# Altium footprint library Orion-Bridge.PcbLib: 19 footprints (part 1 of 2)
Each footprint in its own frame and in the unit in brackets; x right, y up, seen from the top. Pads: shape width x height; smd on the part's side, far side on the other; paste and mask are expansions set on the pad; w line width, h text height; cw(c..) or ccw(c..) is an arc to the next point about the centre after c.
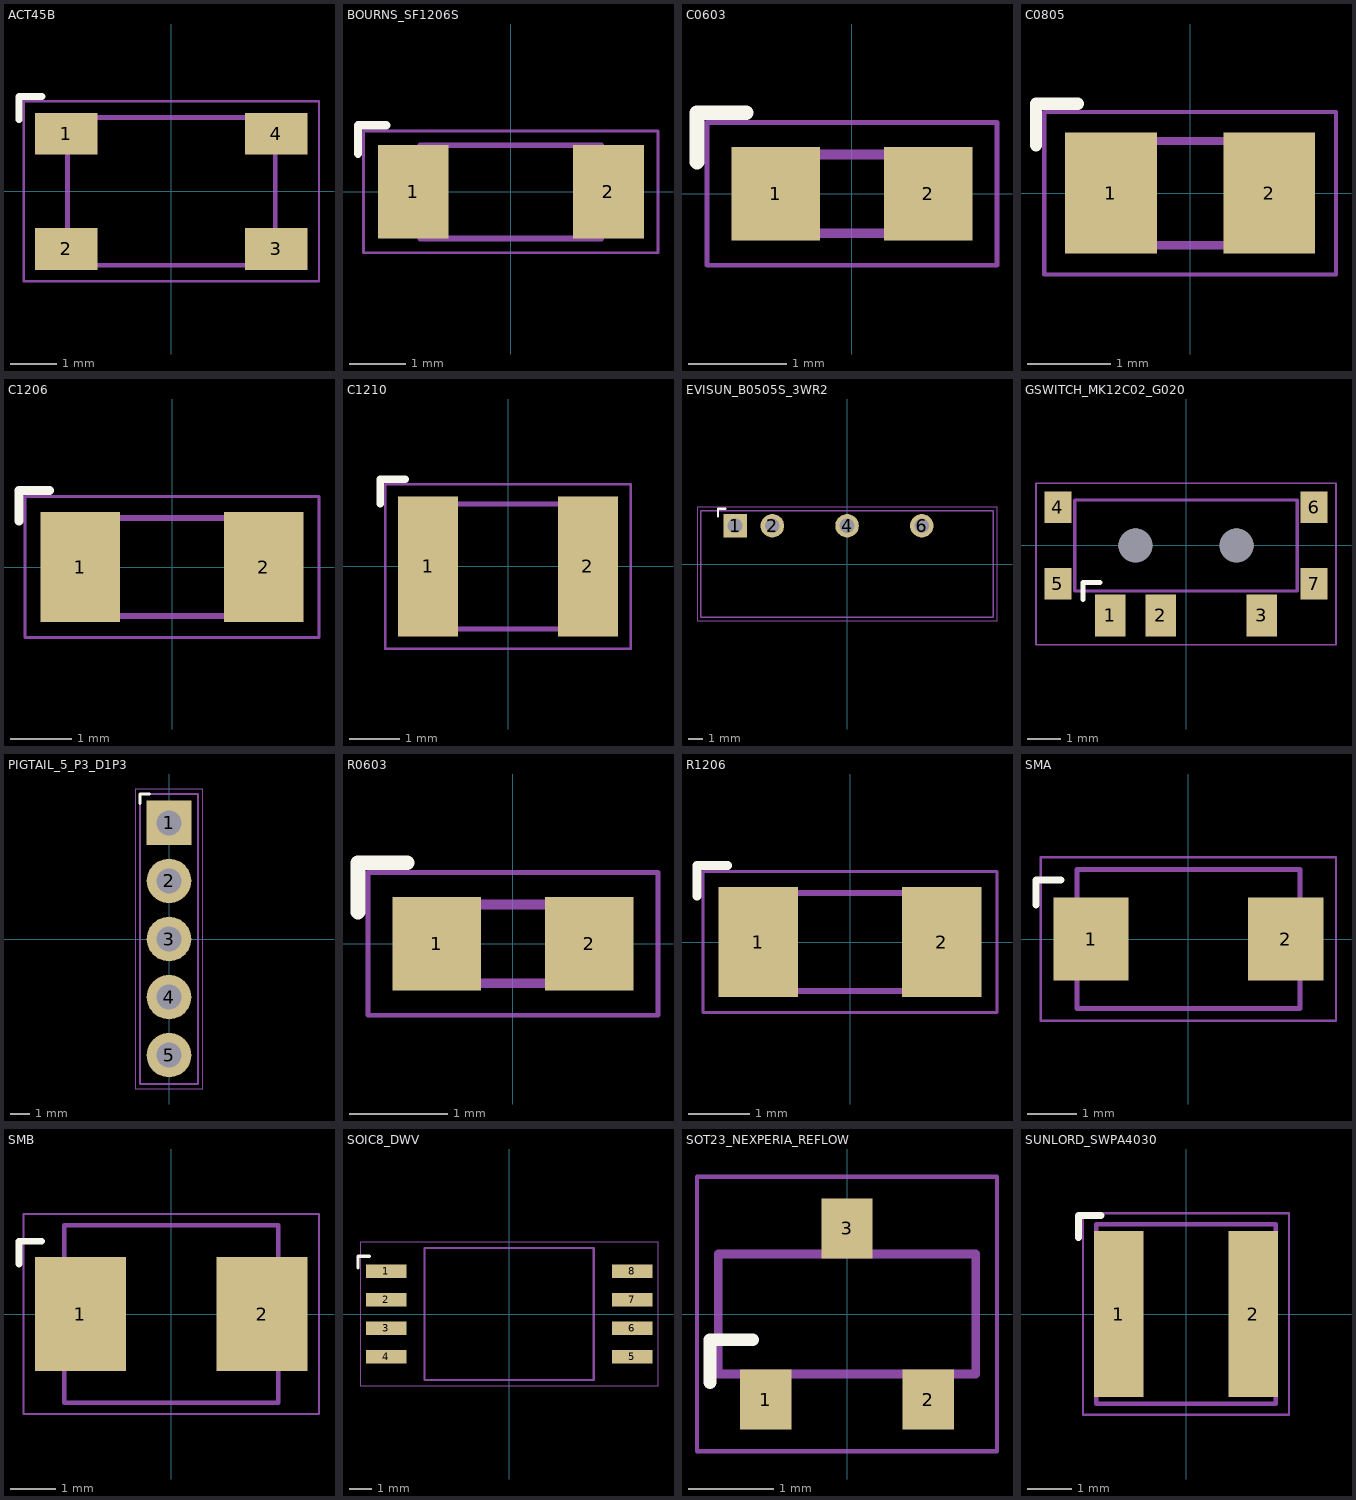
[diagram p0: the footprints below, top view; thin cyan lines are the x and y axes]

## ACT45B [mm] "TDK ACT45B recommended lands; windings 1-4 and 2-3"
height 2.8
pads (4):
  rect 1.35x0.9 smd: 1(-2.275,1.25) 2(-2.275,-1.25) 3(2.275,-1.25) 4(2.275,1.25)
Top Overlay:
  lines w0.15: -3.3,1.55 -3.3,2.05 -2.8,2.05
Component bodies:
  lines w0.1: -2.25,-1.6 2.25,-1.6 2.25,1.6 -2.25,1.6 -2.25,-1.6
Courtyards:
  lines w0.05: -3.2,-1.95 3.2,-1.95 3.2,1.95 -3.2,1.95 -3.2,-1.95
3D body: height 2.8, standoff 0.08, extent -2.25,-1.6 2.25,1.6
3D body: height 0.22, standoff 0.03, extent -2.525,1.01 -1.95,1.49
3D body: height 0.22, standoff 0.03, extent -2.525,-1.49 -1.95,-1.01
3D body: height 0.22, standoff 0.03, extent 1.95,-1.49 2.525,-1.01
3D body: height 0.22, standoff 0.03, extent 1.95,1.01 2.525,1.49

## BOURNS_SF1206S [mm] "Bourns SF-1206S recommended land pattern: total X span 4.7, inner gap 2.2, pad Y 1.65; maximum body envelope. No polarity."
height 0.7
pads (2):
  rect 1.25x1.65 smd: 1(-1.725,0) 2(1.725,0)
Top Overlay:
  lines w0.15: -2.7,0.675 -2.7,1.175 -2.2,1.175
Component bodies:
  lines w0.1: -1.6,-0.825 1.6,-0.825 1.6,0.825 -1.6,0.825 -1.6,-0.825
Courtyards:
  lines w0.05: -2.6,-1.075 2.6,-1.075 2.6,1.075 -2.6,1.075 -2.6,-1.075
3D body: height 0.7, standoff 0.08, extent -1.6,-0.825 1.6,0.825
3D body: height 0.71, standoff 0.03, extent -1.6,-0.833 -1.22,0.833
3D body: height 0.71, standoff 0.03, extent 1.22,-0.833 1.6,0.833

## C0603 [mm] "IPC-style 0603 solder lands; selected MPN dimensions reviewed separately."
height 0.8
pads (2):
  rect 0.9x0.95 smd: 1(-0.775,0) 2(0.775,0)
Top Overlay:
  lines w0.15: -1.575,0.325 -1.575,0.825 -1.075,0.825
Component bodies:
  lines w0.1: -0.8,-0.4 0.8,-0.4 0.8,0.4 -0.8,0.4 -0.8,-0.4
Courtyards:
  lines w0.05: -1.475,-0.725 1.475,-0.725 1.475,0.725 -1.475,0.725 -1.475,-0.725
3D body: height 0.8, standoff 0.08, extent -0.8,-0.4 0.8,0.4
3D body: height 0.81, standoff 0.03, extent -0.8,-0.407 -0.512,0.407
3D body: height 0.81, standoff 0.03, extent 0.512,-0.407 0.8,0.407

## C0805 [mm] "IPC-style 0805 solder lands; selected MPN dimensions reviewed separately."
height 0.8
pads (2):
  rect 1.1x1.45 smd: 1(-0.95,0) 2(0.95,0)
Top Overlay:
  lines w0.15: -1.85,0.575 -1.85,1.075 -1.35,1.075
Component bodies:
  lines w0.1: -1,-0.625 1,-0.625 1,0.625 -1,0.625 -1,-0.625
Courtyards:
  lines w0.05: -1.75,-0.975 1.75,-0.975 1.75,0.975 -1.75,0.975 -1.75,-0.975
3D body: height 0.8, standoff 0.08, extent -1,-0.625 1,0.625
3D body: height 0.81, standoff 0.03, extent -1,-0.633 -0.64,0.633
3D body: height 0.81, standoff 0.03, extent 0.64,-0.633 1,0.633

## C1206 [mm] "IPC-style 1206 solder lands; selected MPN dimensions reviewed separately."
height 1.5
pads (2):
  rect 1.3x1.8 smd: 1(-1.5,0) 2(1.5,0)
Top Overlay:
  lines w0.15: -2.5,0.75 -2.5,1.25 -2,1.25
Component bodies:
  lines w0.1: -1.6,-0.8 1.6,-0.8 1.6,0.8 -1.6,0.8 -1.6,-0.8
Courtyards:
  lines w0.05: -2.4,-1.15 2.4,-1.15 2.4,1.15 -2.4,1.15 -2.4,-1.15
3D body: height 1.5, standoff 0.08, extent -1.6,-0.8 1.6,0.8
3D body: height 1.52, standoff 0.03, extent -1.6,-0.807 -1.22,0.807
3D body: height 1.52, standoff 0.03, extent 1.22,-0.807 1.6,0.807

## C1210 [mm] "Samsung CL32B106KBJNNNE body3.2x2.5mm, nominal1210 land pattern selected."
height 2.7
pads (2):
  rect 1.2x2.8 smd: 1(-1.6,0) 2(1.6,0)
Top Overlay:
  lines w0.15: -2.55,1.25 -2.55,1.75 -2.05,1.75
Component bodies:
  lines w0.1: -1.6,-1.25 1.6,-1.25 1.6,1.25 -1.6,1.25 -1.6,-1.25
Courtyards:
  lines w0.05: -2.45,-1.65 2.45,-1.65 2.45,1.65 -2.45,1.65 -2.45,-1.65
3D body: height 2.7, standoff 0.08, extent -1.6,-1.25 1.6,1.25
3D body: height 2.72, standoff 0.03, extent -1.6,-1.258 -1.22,1.258
3D body: height 2.72, standoff 0.03, extent 1.22,-1.258 1.6,1.258

## EVISUN_B0505S_3WR2 [mm] "EVISUN p4: nominal19.65x7x10.16mm, unspecified body tolerance+/-0.25mm, lead1 x=2.21 from body left, pitch1-2=2.54/2-4=5.08/4-6=5.08mm. Pin row .90mm from long body edge. Bottom view mirrored vertically to PCB TOP: row Y=+2.60mm. Finished holes1.00mm, annulus.30mm. Primary/secondary pad copper gap3.48mm."
height 10.41
pads (4):
  rect 1.6x1.6 hole 1 paste-10: 1(-7.615,2.6)
  round 1.6 hole 1 paste-10: 2(-5.075,2.6) 4(0.005,2.6) 6(5.085,2.6)
Top Overlay:
  lines w0.15: -8.765,3.25 -8.765,3.75 -8.265,3.75
Component bodies:
  lines w0.1: -9.95,-3.625 9.95,-3.625 9.95,3.625 -9.95,3.625 -9.95,-3.625
Courtyards:
  lines w0.05: -10.2,-3.875 10.2,-3.875 10.2,3.875 -10.2,3.875 -10.2,-3.875
3D body: height 10.31, standoff 0.15, extent -9.825,-3.5 9.825,3.5
3D body: height 10.33, standoff 10.31, extent -8.2,-2.55 8.2,2.55
3D body: height 0.45, standoff -2.5, extent -7.865,2.35 -7.365,2.85
3D body: height 0.45, standoff -2.5, extent -5.325,2.35 -4.825,2.85
3D body: height 0.45, standoff -2.5, extent -0.245,2.35 0.255,2.85
3D body: height 0.45, standoff -2.5, extent 4.835,2.35 5.335,2.85

## GSWITCH_MK12C02_G020 [mm] "All shell tabs tied only to GND_LOGIC. No paste in NPTH. Keep travel envelope clear. Pin numbers1/2/3 assigned left/common/right as manufacturer circuit A/B; mounting pads4-7 are local library assignments."
height 1.4
pads (9):
  rect 0.9x1.25 smd: 1(-2.25,-2.075) 2(-0.75,-2.075) 3(2.25,-2.075)
  rect 0.8x0.93 smd: 4(-3.8,1.135) 5(-3.8,-1.135) 6(3.8,1.135) 7(3.8,-1.135)
  round 1 hole 1 unplated paste-10: ""(-1.5,0) ""(1.5,0)
Top Overlay:
  lines w0.15: -3.05,-1.6 -3.05,-1.1 -2.55,-1.1
Component bodies:
  lines w0.1: -3.3,-1.35 3.3,-1.35 3.3,1.35 -3.3,1.35 -3.3,-1.35
Courtyards:
  lines w0.05: -4.45,-2.95 4.45,-2.95 4.45,1.85 -4.45,1.85 -4.45,-2.95
3D body: height 1.25, standoff 0.05, extent -3.3,-1.35 3.3,1.35
3D body: height 1.4, standoff 1.25, extent -3.25,-1.3 3.25,1.3
3D body: height 1.25, standoff 0.15, extent -1.4,1.3 -0.1,3.35
3D body: height 0.15, standoff 0.02, extent -2.7,-2.7 -1.8,-1.45
3D body: height 0.15, standoff 0.02, extent -1.2,-2.7 -0.3,-1.45
3D body: height 0.15, standoff 0.02, extent 1.8,-2.7 2.7,-1.45
3D body: height 0.15, standoff 0.02, extent -4.2,0.67 -3.4,1.6
3D body: height 0.15, standoff 0.02, extent -4.2,-1.6 -3.4,-0.67
3D body: height 0.15, standoff 0.02, extent 3.4,0.67 4.2,1.6
3D body: height 0.15, standoff 0.02, extent 3.4,-1.6 4.2,-0.67

## PIGTAIL_5_P3_D1P3 [mm] "Designed carrier wire-solder interface, 3.0 pitch, 1.3 finished-hole target, 0.5 radial annulus. Pin numbering is logical NMEA: 1 shield, 2 NET-S, 3 NET-C, 4 CAN-H, 5 CAN-L. Cable and strain relief still require a physical selection."
height 3
pads (5):
  rect 2.3x2.3 hole 1.3 paste-10: 1(0,6)
  round 2.3 hole 1.3 paste-10: 2(0,3) 3(0,0) 4(0,-3) 5(0,-6)
Top Overlay:
  lines w0.15: -1.5,7 -1.5,7.5 -1,7.5
Component bodies:
  lines w0.1: -1.5,-7.5 1.5,-7.5 1.5,7.5 -1.5,7.5 -1.5,-7.5
Courtyards:
  lines w0.05: -1.75,-7.75 1.75,-7.75 1.75,7.75 -1.75,7.75 -1.75,-7.75
3D body: height 0.06, standoff 0.03, extent -1.15,4.85 1.15,5.03
3D body: height 0.06, standoff 0.03, extent -1.15,6.97 1.15,7.15
3D body: height 0.06, standoff 0.03, extent -1.15,5.03 -0.97,6.97
3D body: height 0.06, standoff 0.03, extent 0.97,5.03 1.15,6.97
3D body: height 0.06, standoff 0.03, extent -1.15,1.85 1.15,2.03
3D body: height 0.06, standoff 0.03, extent -1.15,3.97 1.15,4.15
3D body: height 0.06, standoff 0.03, extent -1.15,2.03 -0.97,3.97
3D body: height 0.06, standoff 0.03, extent 0.97,2.03 1.15,3.97
3D body: height 0.06, standoff 0.03, extent -1.15,-1.15 1.15,-0.97
3D body: height 0.06, standoff 0.03, extent -1.15,0.97 1.15,1.15
3D body: height 0.06, standoff 0.03, extent -1.15,-0.97 -0.97,0.97
3D body: height 0.06, standoff 0.03, extent 0.97,-0.97 1.15,0.97
3D body: height 0.06, standoff 0.03, extent -1.15,-4.15 1.15,-3.97
3D body: height 0.06, standoff 0.03, extent -1.15,-2.03 1.15,-1.85
3D body: height 0.06, standoff 0.03, extent -1.15,-3.97 -0.97,-2.03
3D body: height 0.06, standoff 0.03, extent 0.97,-3.97 1.15,-2.03
3D body: height 0.06, standoff 0.03, extent -1.15,-7.15 1.15,-6.97
3D body: height 0.06, standoff 0.03, extent -1.15,-5.03 1.15,-4.85
3D body: height 0.06, standoff 0.03, extent -1.15,-6.97 -0.97,-5.03
3D body: height 0.06, standoff 0.03, extent 0.97,-6.97 1.15,-5.03

## R0603 [mm] "IPC-style 0603 solder lands; selected MPN dimensions reviewed separately."
height 0.8
pads (2):
  rect 0.9x0.95 smd: 1(-0.775,0) 2(0.775,0)
Top Overlay:
  lines w0.15: -1.575,0.325 -1.575,0.825 -1.075,0.825
Component bodies:
  lines w0.1: -0.8,-0.4 0.8,-0.4 0.8,0.4 -0.8,0.4 -0.8,-0.4
Courtyards:
  lines w0.05: -1.475,-0.725 1.475,-0.725 1.475,0.725 -1.475,0.725 -1.475,-0.725
3D body: height 0.8, standoff 0.08, extent -0.8,-0.4 0.8,0.4
3D body: height 0.81, standoff 0.03, extent -0.8,-0.407 -0.512,0.407
3D body: height 0.81, standoff 0.03, extent 0.512,-0.407 0.8,0.407

## R1206 [mm] "IPC-style 1206 solder lands; selected MPN dimensions reviewed separately."
height 1.5
pads (2):
  rect 1.3x1.8 smd: 1(-1.5,0) 2(1.5,0)
Top Overlay:
  lines w0.15: -2.5,0.75 -2.5,1.25 -2,1.25
Component bodies:
  lines w0.1: -1.6,-0.8 1.6,-0.8 1.6,0.8 -1.6,0.8 -1.6,-0.8
Courtyards:
  lines w0.05: -2.4,-1.15 2.4,-1.15 2.4,1.15 -2.4,1.15 -2.4,-1.15
3D body: height 1.5, standoff 0.08, extent -1.6,-0.8 1.6,0.8
3D body: height 1.52, standoff 0.03, extent -1.6,-0.807 -1.22,0.807
3D body: height 1.52, standoff 0.03, extent 1.22,-0.807 1.6,0.807

## SMA [mm] "MDD SS12-SS1200 Rev2025A3 p3 / SS22-SS2200 Rev2024A4 p3 suggested SMA pattern: pad1.52x1.68, centrepitch3.93, innergap2.41, totalX5.45mm. Maxbody4.5x2.8x2.45; pin1Kleft,2Aright. Visually checked selected C2480/C14238 PDFs."
height 2.45
pads (2):
  rect 1.52x1.68 smd: 1(-1.965,0) 2(1.965,0)
Top Overlay:
  lines w0.15: -3.075,0.69 -3.075,1.19 -2.575,1.19
Component bodies:
  lines w0.1: -2.25,-1.4 2.25,-1.4 2.25,1.4 -2.25,1.4 -2.25,-1.4
Courtyards:
  lines w0.05: -2.975,-1.65 2.975,-1.65 2.975,1.65 -2.975,1.65 -2.975,-1.65
3D body: height 2.45, standoff 0.08, extent -2.25,-1.4 2.25,1.4
3D body: height 0.2, standoff 0.03, extent -2.54,-0.84 -1.39,0.84
3D body: height 0.2, standoff 0.03, extent 1.39,-0.84 2.54,0.84
3D body: height 2.46, standoff 2.45, extent -1.52,-1.372 -1.27,1.372

## SMB [mm] "BORN SMBJ Series Rev2022-Jan-1-A p7 manufacturer pattern: pad2.0x2.5mm, innergap2.0mm, centres+/-2.0mm; maxbody4.7x3.9x2.5; pin1Kleft,2Aright. Visually checked selected C152104 PDF."
height 2.5
pads (2):
  rect 2x2.5 smd: 1(-2,0) 2(2,0)
Top Overlay:
  lines w0.15: -3.35,1.1 -3.35,1.6 -2.85,1.6
Component bodies:
  lines w0.1: -2.35,-1.95 2.35,-1.95 2.35,1.95 -2.35,1.95 -2.35,-1.95
Courtyards:
  lines w0.05: -3.25,-2.2 3.25,-2.2 3.25,2.2 -3.25,2.2 -3.25,-2.2
3D body: height 2.5, standoff 0.08, extent -2.35,-1.95 2.35,1.95
3D body: height 0.2, standoff 0.03, extent -2.575,-1.05 -1.425,1.05
3D body: height 0.2, standoff 0.03, extent 1.425,-1.05 2.575,1.05
3D body: height 2.51, standoff 2.5, extent -1.582,-1.911 -1.332,1.911

## SOIC8_DWV [mm] "TI DWV0008A manufacturer land pattern; pin 1 upper left"
height 2.8
pads (8):
  rect 1.8x0.6 smd: 1(-5.45,1.905) 2(-5.45,0.635) 3(-5.45,-0.635) 4(-5.45,-1.905) 5(5.45,-1.905) 6(5.45,-0.635) 7(5.45,0.635) 8(5.45,1.905)
Top Overlay:
  lines w0.15: -6.7,2.055 -6.7,2.555 -6.2,2.555
Component bodies:
  lines w0.1: -3.75,-2.925 3.75,-2.925 3.75,2.925 -3.75,2.925 -3.75,-2.925
Courtyards:
  lines w0.05: -6.6,-3.175 6.6,-3.175 6.6,3.175 -6.6,3.175 -6.6,-3.175
3D body: height 2.8, standoff 0.08, extent -3.75,-2.925 3.75,2.925
3D body: height 0.22, standoff 0.03, extent -5.7,1.665 -3.45,2.145
3D body: height 0.22, standoff 0.03, extent -5.7,0.395 -3.45,0.875
3D body: height 0.22, standoff 0.03, extent -5.7,-0.875 -3.45,-0.395
3D body: height 0.22, standoff 0.03, extent -5.7,-2.145 -3.45,-1.665
3D body: height 0.22, standoff 0.03, extent 3.45,-2.145 5.7,-1.665
3D body: height 0.22, standoff 0.03, extent 3.45,-0.875 5.7,-0.395
3D body: height 0.22, standoff 0.03, extent 3.45,0.395 5.7,0.875
3D body: height 0.22, standoff 0.03, extent 3.45,1.665 5.7,2.145
3D body: height 2.82, standoff 2.8, extent -2.38,1.625 -2.12,1.885

## SOT23_NEXPERIA_REFLOW [mm] "Nexperia SOT23 reflow footprint Fig10: 0.6 x 0.7 copper lands, 1.9 pin pitch and 2.0 row centres. Drawing is rotated 180 degrees to match existing top-view pin1 lower left, pin2 lower right, pin3 upper centre. Paste suggested0.5 x0.6, mask opening1.0 x1.0; set fabrication-specific expansions accordingly."
height 1.1
pads (3):
  rect 0.6x0.7 smd: 1(-0.95,-1) 2(0.95,-1) 3(0,1)
Top Overlay:
  lines w0.15: -1.6,-0.8 -1.6,-0.3 -1.1,-0.3
Component bodies:
  lines w0.1: -1.5,-0.7 1.5,-0.7 1.5,0.7 -1.5,0.7 -1.5,-0.7
Courtyards:
  lines w0.05: -1.75,-1.6 1.75,-1.6 1.75,1.6 -1.75,1.6 -1.75,-1.6
3D body: height 1.1, standoff 0.08, extent -1.5,-0.7 1.5,0.7
3D body: height 0.22, standoff 0.03, extent -1.175,-1.25 -0.725,-0.4
3D body: height 0.22, standoff 0.03, extent 0.725,-1.25 1.175,-0.4
3D body: height 0.22, standoff 0.03, extent -0.225,0.4 0.225,1.25
3D body: height 1.11, standoff 1.1, extent -1.03,-0.55 -0.77,-0.29

## SUNLORD_SWPA4030 [mm] "Sunlord SWPA datasheet2025-05-08 p2 recommended SWPA4030S pattern: gap1.9, padwidth1.1, padheight3.7."
height 3
pads (2):
  rect 1.1x3.7 smd: 1(-1.5,0) 2(1.5,0)
Top Overlay:
  lines w0.15: -2.4,1.7 -2.4,2.2 -1.9,2.2
Component bodies:
  lines w0.1: -2,-2 2,-2 2,2 -2,2 -2,-2
Courtyards:
  lines w0.05: -2.3,-2.25 2.3,-2.25 2.3,2.25 -2.3,2.25 -2.3,-2.25
3D body: height 3, standoff 0.1, extent -2,-2 2,2
3D body: height 3.02, standoff 3, extent -1.6,-1.6 1.6,1.6
3D body: height 0.18, standoff 0.03, extent -1.94,-1.48 -1.06,1.48
3D body: height 0.18, standoff 0.03, extent 1.06,-1.48 1.94,1.48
